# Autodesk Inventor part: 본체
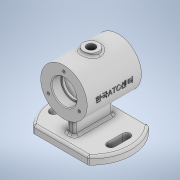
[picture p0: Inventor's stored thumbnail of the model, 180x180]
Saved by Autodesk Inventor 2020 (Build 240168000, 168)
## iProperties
Created: 2021-09
Part Number: 본체
Material: 일반
Document SubType Name: Modeling
Designer: Administrator
Density: 1 g/cm^3
Appearance: 기본값
Mass: 173.2 g
Surface Area: 487.332 cm^2
Volume: 173.2 cm^3
Author: Administrator
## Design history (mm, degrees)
sketch "스케치1"
  geometry: C1 r 52.5 at (0, 0); 1 further point
  constraints: 1 centre point, 1 coincident
  dimensions: "d4" = 105 diameter of C1
extrude "돌출1" new body sketch "스케치1" distance "d1" = 10; taper "d2" = 0 deg
sketch "스케치2"
  geometry: L1 (-81.213, -38.87)-(81.213, -38.87); L2 (81.213, -38.87)-(81.213, 36.13); L3 (81.213, 36.13)-(-81.213, 36.13); L4 (-81.213, 36.13)-(-81.213, -38.87); L5 (-81.213, -38.87)-(81.213, 36.13); L6 (81.213, -38.87)-(-81.213, 36.13); C1 r 52.5 at (0, 0) reference; 6 further points
  constraints: 12 end point, 2 midpoint, 2 parallel, 1 horizontal, 1 perpendicular
  dimensions: "d5" = 75 distance of L2.end L1.end
extrude "돌출2" cut sketch "스케치2" distance "d6" = 10; taper "d7" = 0 deg
sketch "스케치3"
  geometry: C1 r 30 at (0, 62); 1 further point
  constraints: 1 centre point
  dimensions: "d9" = 60 diameter of C1; "d10" = 62 distance of point (0, 0) C1.centre
extrude "돌출3" join sketch "스케치3" stored distance "d11" = 70; taper "d12" = 0 deg
sketch "스케치4"
  geometry: L1 (92, 35)-(32, 35) reference; L2 (62, 35)-(62, -35); L3 (32, -35)-(92, -35) reference; L4 (78, 35)-(78, 23); L5 (78, 23)-(76, 23); L6 (76, 23)-(76, 20); L7 (76, 20)-(87, 20); L8 (87, 20)-(87, -20); L9 (87, -20)-(76, -20); L10 (76, -20)-(76, -23); L11 (76, -23)-(78, -23); L12 (78, -23)-(78, -35); 1 further point
  constraints: 20 end point, 6 perpendicular, 6 point on line, 2 midpoint, 1 vertical
  dimensions: "d13" = 32 diameter of L4 L2; "d14" = 28 diameter of L6 L2; "d15" = 50 diameter of L8 L2; "d16" = 12 distance between parallel lines of L1 L5; "d17" = 12 distance between parallel lines of L3 L11; "d18" = 40 distance between parallel lines of L9 L7; "d19" = 3 distance between parallel lines of L5 L7
revolve "회전1" sketch "스케치4" stored, may be unused: angle "d20" = 90 deg
sketch "스케치5"
  geometry: L1 (-5, 23.63)-(5, 23.63); L2 (5, 23.63)-(5, -26.37); L3 (5, -26.37)-(-5, -26.37); L4 (-5, -26.37)-(-5, 23.63); L5 (35.29, -38.87)-(-35.29, -38.87) reference; A1 r 52.5 centre (0, 0) between (35.29, -38.87) and (38.09, 36.13) reference; A2 r 52.5 centre (0, 0) between (-38.09, 36.13) and (-35.29, -38.87) reference; 1 further point
  constraints: 8 end point, 2 parallel, 1 horizontal, 1 perpendicular
  dimensions: "d21" = 10 distance of L2.end L3.end; "d22" = 50 distance of L1.end L2.end; "d67" = 12.5 distance between parallel lines of L5 L3; "d68" = 47.5 distance edge to line of A2 L4
extrude "돌출4" join sketch "스케치5" stored distance "d23" = 70; taper "d24" = 0 deg
node "작업 평면2"
  node "작업 평면1"
sketch "스케치6"
  geometry: C1 r 10 at (0, 0); 1 further point
  constraints: 1 centre point, 1 coincident
  dimensions: "d26" = 10 radius of C1
extrude "돌출5" join sketch "스케치6" stored distance "d27" = 70; taper "d28" = 0 deg
sketch "스케치7"
  geometry: C1 r 10 at (0, 0) reference; 2 further points
  constraints: 1 coincident
hole "구멍1" sketch "스케치7" at (0, 0) diameter "d29" = 10.917; stored, may be unused: countersink angle "d33" = 90 deg, drill point angle "d35" = 0 deg; dims "d30" = 24, "d31" = 4, "d32" = 2, "d34" = 29.1
sketch "스케치8" dims "d36" = 23
  geometry: C1 r 14 at (0, 0) reference; 3 further points
  constraints: 1 coincident, 1 vertical alignment, 2 other
hole "구멍2" sketch "스케치8" at (0, 23) diameter "d37" = 3.45873; stored, may be unused: countersink angle "d41" = 90 deg, drill point angle "d43" = 118 deg; dims "d38" = 8, "d39" = 4, "d40" = 2, "d42" = 10
sketch "스케치9"
  geometry: L1 (-37, 8.63)-(-37, -11.37); L2 (-42, 8.63)-(-42, -11.37); L3 (-32, -11.37)-(-32, 8.63); L4 (-38.09, 36.13)-(38.09, 36.13) reference; A1 r 5 centre (-37, 8.63) between (-32, 8.63) and (-42, 8.63); A2 r 5 centre (-37, -11.37) between (-42, -11.37) and (-32, -11.37); 2 further points
  constraints: 8 end point, 4 point on circle, 4 tangent, 2 centre point, 1 midpoint, 1 parallel, 1 vertical
  dimensions: "d47" = 37 horizontal distance of point (-37, -1.37) point (0, 0); "d48" = 10 distance between parallel lines of L2 L3; "d49" = 20 distance of L1.end L1.start; "d50" = 37.5 distance from line of L4 point (-37, -1.37)
extrude "돌출6" cut sketch "스케치9" distance "d51" = 70; taper "d52" = 0 deg
fillet "모깎기1" dims "d53" = 3
fillet "모깎기2" dims "d54" = 3
fillet "모깎기3" dims "d55" = 3
fillet "모깎기4" dims "d56" = 0.3
chamfer "모따기1" distance "d57" = 1; stored, may be unused: second distance "d58" = 2, angle "d59" = 45 deg
node "작업 평면5"
  node "작업 평면4"
sketch "스케치10"
  geometry: L1 (30, 35)-(-30, 35) reference; L2 (30, -35)-(30, 35) reference; 2 further points
  constraints: 1 other
  dimensions: "d61" = 35 distance from line of L1 point (0, 0); "d62" = 30 distance from line of point (0, 0) L2
feature "엠보싱1" sketch "스케치10" dims "d63" = 0.5, "d64" = 0
fillet "모깎기5" dims "d65" = 3
node "솔리드1"
pattern_circular "원형 패턴1" dims angle "d45" = 360 deg
mirror "미러1"
mirror "미러2"
node "작업 평면3"
feature "A9D066F2-1C7D-4E18-AEED-F7BC21143FA4" dims "d29" = 10.917, "d30" = 24, "d31" = 4, "d32" = 2, "d33" = 90 deg, "d34" = 29.1, "d35" = 0
other parameters: "d25" = 3, "d60" = 24.5
